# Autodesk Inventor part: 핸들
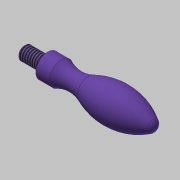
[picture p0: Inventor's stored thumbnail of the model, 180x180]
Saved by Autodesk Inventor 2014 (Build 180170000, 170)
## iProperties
Created: 2019-10
Part Number: 핸들
Material: 스테인리스강
Document SubType Name: Modeling
Designer: mduedu
Density: 1 g/cm^3
Appearance: Violet
Author: mduedu
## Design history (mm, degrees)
sketch "스케치1"
  geometry: L1 (0, 0)-(0, 2); L2 (0, 2)-(7, 2); L3 (7, 2)-(7, 3.5); L4 (7, 3.5)-(11, 3.5); L5 (0, 0)-(39, 0); A1 r 9.5 centre (15.243, 12) between (11, 3.5) and (19.07, 3.305); A2 r 20 centre (27.128, -15) between (38.049, 1.754) and (19.07, 3.305); A3 r 2.094 centre (36.906, 0) between (39, 0) and (38.049, 1.754)
  constraints: 10 end point, 6 point on circle, 3 centre point, 3 parallel, 2 tangent, 1 perpendicular, 1 point on line, 1 vertical
  dimensions: "d0" = 39 distance of L1.start L5.end; "d1" = 4 diameter of L2 L5; "d2" = 7 diameter of L4 L5; "d3" = 7 distance of L1.end L2.end; "d4" = 4 distance of L3.end L4.end; "d5" = 5 dimension on A1 L5; "d6" = 9.5 radius of A1; "d7" = 10 dimension on A2 L5; "d8" = 20 radius of A2
revolve "회전1" sketch "스케치1" stored, may be unused: angle "d9" = 90 deg
feature "스레드1" dims "d10" = 6, "d11" = 0
chamfer "모따기1" distance "d12" = 0.5; stored, may be unused: second distance "d13" = 2, angle "d14" = 45 deg
node "솔리드1"
